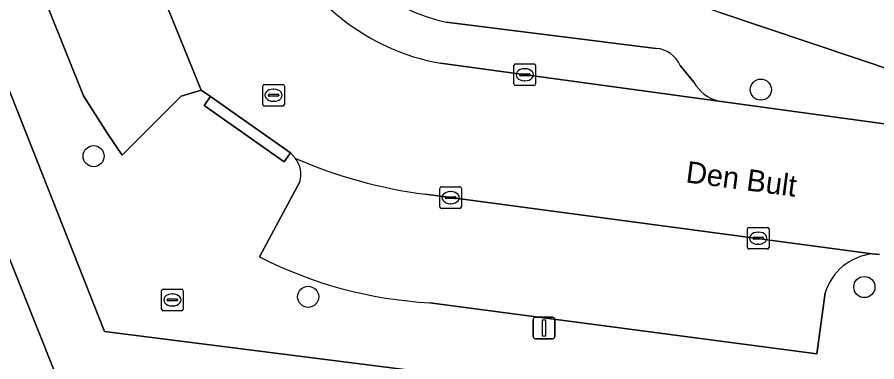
# Model space of a CAD drawing. Extents: x 159716 to 160783, y 383290 to 384031.
# Drawn here: x 160012.06 to 160051.81, y 383381.02 to 383396.98 of the extents above; entities that cross this region are included whole.
import ezdxf

# ---------------------------------------------------------------- set-up
doc = ezdxf.new("R2010")
doc.units = 0
for name, color, linetype in [('IMGEO_Boom', 7, 'Continuous'), ('IMGEO_Brandkraan', 7, 'Continuous'), ('IMGEO_Erf', 7, 'Continuous'), ('IMGEO_Kolk', 7, 'Continuous'), ('IMGEO_Lichtmast', 7, 'Continuous'), ('IMGEO_Openbare_ruimte_label', 7, 'Continuous'), ('IMGEO_Pand', 7, 'Continuous'), ('IMGEO_Parkeervlak_open', 7, 'Continuous'), ('IMGEO_Rijbaan_lokaal_open', 7, 'Continuous'), ('IMGEO_Rioolput', 7, 'Continuous'), ('IMGEO_Voetpad_open', 7, 'Continuous')]:
    doc.layers.add(name, color=color, linetype=linetype)

msp = doc.modelspace()

# ---------------------------------------------------------------- linework, layer by layer
at = {"layer": 'IMGEO_Boom'}
for centre in [(160046.451, 383393.623), (160015.592, 383390.544), (160051.24, 383384.484), (160025.516, 383384.034)]:
    msp.add_circle(centre, 0.489, dxfattribs=at)
at = {"layer": 'IMGEO_Brandkraan'}
for p, q in [((160018.738, 383383.463), (160018.738, 383384.315)), ((160018.813, 383384.389), (160019.665, 383384.389)), ((160019.739, 383384.315), (160019.739, 383383.463)), ((160018.997, 383383.883), (160018.997, 383383.895)), ((160019.435, 383383.846), (160019.037, 383383.846)), ((160019.04, 383383.932), (160019.438, 383383.932)), ((160019.226, 383384.169), (160019.251, 383384.169)), ((160019.481, 383383.895), (160019.481, 383383.883)), ((160019.249, 383383.609), (160019.224, 383383.609)), ((160019.665, 383383.389), (160018.813, 383383.389))]:
    msp.add_line(p, q, dxfattribs=at)
for points in [[(160018.738, 383383.463), (160018.738, 383384.315)], [(160018.813, 383384.389), (160019.665, 383384.389)], [(160019.739, 383384.315), (160019.739, 383383.463)], [(160019.665, 383383.389), (160018.813, 383383.389)]]:
    msp.add_lwpolyline(points, dxfattribs=at)
for centre, radius, start, end in [((160018.815, 383384.313), 0.0765, 91.552, 178.448), ((160018.815, 383384.313), 0.0765, 91.552, 178.448), ((160019.663, 383384.313), 0.0765, 1.552, 88.448), ((160019.663, 383384.313), 0.0765, 1.552, 88.448), ((160019.037, 383383.892), 0.0403, 85.8775, 175.7526), ((160019.034, 383383.882), 0.0366, 178.938, 274.7102), ((160019.438, 383383.889), 0.043, 264.8664, 352.4533), ((160019.442, 383383.894), 0.0386, 1.7309, 96.639), ((160018.815, 383383.465), 0.0765, 181.552, 268.448), ((160018.815, 383383.465), 0.0765, 181.552, 268.448), ((160019.663, 383383.465), 0.0765, 271.552, 358.448), ((160019.663, 383383.465), 0.0765, 271.552, 358.448)]:
    msp.add_arc(centre, radius, start, end, dxfattribs=at)
for centre, major_axis, ratio, start_param, end_param in [((160019.225, 383383.889), (-0.387, 0.002), 0.722429, 4.712389, 7.853982), ((160019.25, 383383.889), (-0.39, 0.002), 0.717154, 1.570796, 4.712389)]:
    msp.add_ellipse(centre, major_axis=major_axis, ratio=ratio, start_param=start_param, end_param=end_param, dxfattribs=at)
at = {"layer": 'IMGEO_Erf'}
for points in [[(160000.81, 383413.031), (160002.876, 383407.864), (160004.895, 383402.814), (160006.914, 383397.764), (160008.934, 383392.713), (160010.953, 383387.663), (160014.825, 383377.98), (160018.263, 383377.541), (160018.539, 383379.697), (160024.297, 383378.96), (160029.935, 383378.239), (160035.574, 383377.518), (160041.212, 383376.797), (160046.85, 383376.076), (160052.624, 383375.337), (160052.976, 383377.756), (160016.099, 383382.429), (160004.346, 383412.176)], [(160044.548, 383397.2), (160052.814, 383394.42)]]:
    msp.add_lwpolyline(points, dxfattribs=at)
at = {"layer": 'IMGEO_Kolk'}
for p, q in [((160035.033, 383393.885), (160035.033, 383394.737)), ((160035.108, 383394.811), (160035.96, 383394.811)), ((160035.521, 383394.591), (160035.546, 383394.591)), ((160036.034, 383394.737), (160036.034, 383393.885)), ((160035.292, 383394.305), (160035.292, 383394.317)), ((160035.73, 383394.268), (160035.332, 383394.268)), ((160035.335, 383394.354), (160035.733, 383394.354)), ((160035.776, 383394.317), (160035.776, 383394.305)), ((160035.96, 383393.811), (160035.108, 383393.811)), ((160035.544, 383394.031), (160035.519, 383394.031)), ((160031.604, 383388.197), (160031.604, 383389.049)), ((160031.679, 383389.123), (160032.531, 383389.123)), ((160032.605, 383389.049), (160032.605, 383388.197)), ((160031.863, 383388.617), (160031.863, 383388.629)), ((160031.906, 383388.666), (160032.304, 383388.666)), ((160032.092, 383388.903), (160032.117, 383388.903)), ((160032.347, 383388.629), (160032.347, 383388.617)), ((160032.301, 383388.58), (160031.903, 383388.58)), ((160032.115, 383388.343), (160032.09, 383388.343)), ((160032.531, 383388.123), (160031.679, 383388.123)), ((160045.829, 383386.32), (160045.829, 383387.172)), ((160045.904, 383387.246), (160046.756, 383387.246)), ((160046.317, 383387.026), (160046.342, 383387.026)), ((160046.83, 383387.172), (160046.83, 383386.32)), ((160046.088, 383386.74), (160046.088, 383386.752)), ((160046.526, 383386.703), (160046.128, 383386.703)), ((160046.131, 383386.789), (160046.529, 383386.789)), ((160046.572, 383386.752), (160046.572, 383386.74)), ((160046.756, 383386.246), (160045.904, 383386.246)), ((160046.34, 383386.466), (160046.315, 383386.466))]:
    msp.add_line(p, q, dxfattribs=at)
for points in [[(160035.033, 383393.885), (160035.033, 383394.737)], [(160035.108, 383394.811), (160035.96, 383394.811)], [(160036.034, 383394.737), (160036.034, 383393.885)], [(160035.96, 383393.811), (160035.108, 383393.811)], [(160031.604, 383388.197), (160031.604, 383389.049)], [(160031.679, 383389.123), (160032.531, 383389.123)], [(160032.605, 383389.049), (160032.605, 383388.197)], [(160032.531, 383388.123), (160031.679, 383388.123)], [(160045.829, 383386.32), (160045.829, 383387.172)], [(160045.904, 383387.246), (160046.756, 383387.246)], [(160046.83, 383387.172), (160046.83, 383386.32)], [(160046.756, 383386.246), (160045.904, 383386.246)]]:
    msp.add_lwpolyline(points, dxfattribs=at)
for centre, radius, start, end in [((160035.11, 383394.735), 0.0765, 91.552, 178.448), ((160035.11, 383394.735), 0.0765, 91.552, 178.448), ((160035.958, 383394.735), 0.0765, 1.552, 88.448), ((160035.958, 383394.735), 0.0765, 1.552, 88.448), ((160035.332, 383394.314), 0.0403, 85.8775, 175.7526), ((160035.329, 383394.304), 0.0366, 178.938, 274.7102), ((160035.733, 383394.311), 0.043, 264.8664, 352.4533), ((160035.737, 383394.316), 0.0386, 1.7309, 96.639), ((160035.11, 383393.887), 0.0765, 181.552, 268.448), ((160035.11, 383393.887), 0.0765, 181.552, 268.448), ((160035.958, 383393.887), 0.0765, 271.552, 358.448), ((160035.958, 383393.887), 0.0765, 271.552, 358.448), ((160031.681, 383389.047), 0.0765, 91.552, 178.448), ((160031.681, 383389.047), 0.0765, 91.552, 178.448), ((160032.529, 383389.047), 0.0765, 1.552, 88.448), ((160032.529, 383389.047), 0.0765, 1.552, 88.448), ((160031.903, 383388.626), 0.0403, 85.8775, 175.7526), ((160031.9, 383388.616), 0.0366, 178.938, 274.7102), ((160032.304, 383388.623), 0.043, 264.8664, 352.4533), ((160032.308, 383388.628), 0.0386, 1.7309, 96.639), ((160031.681, 383388.199), 0.0765, 181.552, 268.448), ((160031.681, 383388.199), 0.0765, 181.552, 268.448), ((160032.529, 383388.199), 0.0765, 271.552, 358.448), ((160032.529, 383388.199), 0.0765, 271.552, 358.448), ((160045.906, 383387.17), 0.0765, 91.552, 178.448), ((160045.906, 383387.17), 0.0765, 91.552, 178.448), ((160046.754, 383387.17), 0.0765, 1.552, 88.448), ((160046.754, 383387.17), 0.0765, 1.552, 88.448), ((160046.128, 383386.749), 0.0403, 85.8775, 175.7526), ((160046.125, 383386.739), 0.0366, 178.938, 274.7102), ((160046.529, 383386.746), 0.043, 264.8664, 352.4533), ((160046.533, 383386.751), 0.0386, 1.7309, 96.639), ((160045.906, 383386.322), 0.0765, 181.552, 268.448), ((160045.906, 383386.322), 0.0765, 181.552, 268.448), ((160046.754, 383386.322), 0.0765, 271.552, 358.448), ((160046.754, 383386.322), 0.0765, 271.552, 358.448)]:
    msp.add_arc(centre, radius, start, end, dxfattribs=at)
for centre, major_axis, ratio, start_param, end_param in [((160035.52, 383394.311), (-0.387, 0.002), 0.722429, 4.712389, 7.853982), ((160035.545, 383394.311), (-0.39, 0.002), 0.717154, 1.570796, 4.712389), ((160032.091, 383388.623), (-0.387, 0.002), 0.722429, 4.712389, 7.853982), ((160032.116, 383388.623), (-0.39, 0.002), 0.717154, 1.570796, 4.712389), ((160046.316, 383386.746), (-0.387, 0.002), 0.722429, 4.712389, 7.853982), ((160046.341, 383386.746), (-0.39, 0.002), 0.717154, 1.570796, 4.712389)]:
    msp.add_ellipse(centre, major_axis=major_axis, ratio=ratio, start_param=start_param, end_param=end_param, dxfattribs=at)
at = {"layer": 'IMGEO_Lichtmast'}
for p, q in [((160036.029, 383383.09), (160036.819, 383383.09)), ((160036.819, 383383.09), (160036.029, 383383.09)), ((160035.929, 383382.19), (160035.929, 383382.99)), ((160035.929, 383382.99), (160035.929, 383382.19)), ((160036.919, 383382.99), (160036.919, 383382.19)), ((160036.919, 383382.19), (160036.919, 383382.99)), ((160036.819, 383382.09), (160036.029, 383382.09)), ((160036.029, 383382.09), (160036.819, 383382.09))]:
    msp.add_line(p, q, dxfattribs=at)
msp.add_lwpolyline([(160036.349, 383382.965), (160036.499, 383382.965), (160036.499, 383382.215), (160036.349, 383382.215), (160036.349, 383382.965)], dxfattribs=at)
for centre, start, end in [((160036.029, 383382.99), 90, 180), ((160036.029, 383382.99), 90, 180), ((160036.819, 383382.99), 0, 90), ((160036.819, 383382.99), 360, 90), ((160036.029, 383382.19), 180, 270), ((160036.029, 383382.19), 180, 270), ((160036.819, 383382.19), 270, 0), ((160036.819, 383382.19), 270, 0)]:
    msp.add_arc(centre, 0.1, start, end, dxfattribs=at)
at = {"layer": 'IMGEO_Pand'}
msp.add_lwpolyline([(160003.449, 383384.662), (160006.055, 383378.145), (160008.19, 383378.998), (160010.623, 383373.014), (160014.825, 383377.98), (160010.953, 383387.663)], close=True, dxfattribs=at)
at = {"layer": 'IMGEO_Parkeervlak_open'}
for points in [[(160010.124, 383414.551), (160007.087, 383413.335), (160015.132, 383393.329), (160016.239, 383391.585), (160016.912, 383390.595), (160019.641, 383393.313), (160020.572, 383393.598), (160016.582, 383403.447), (160011.17, 383416.862)], [(160041.606, 383395.532), (160031.897, 383396.753)], [(160031.637, 383394.841), (160044.505, 383393.088)], [(160043.345, 383393.971), (160042.723, 383394.733)], [(160025.127, 383389.354), (160023.261, 383385.888)], [(160051.595, 383386.022), (160030.94, 383388.777)], [(160031.145, 383383.758), (160049.047, 383381.392), (160049.428, 383384.224)]]:
    msp.add_lwpolyline(points, dxfattribs=at)
for centre, radius, start, end in [((160033.754, 383405.228), 8.676, 205.1112, 257.6415), ((160033.452, 383404.956), 10.276, 203.0028, 259.8259), ((160041.507, 383394.213), 1.323, 23.1563, 85.6907), ((160044.989, 383394.928), 1.902, 210.1891, 255.2536), ((160033.905, 383411.181), 22.6, 246.5895, 262.4606), ((160023.975, 383389.704), 1.204, 343.1064, 37.8275), ((160032.179, 383403.243), 19.512, 242.802, 266.961), ((160051.89, 383383.462), 2.577, 96.565, 162.8012)]:
    msp.add_arc(centre, radius, start, end, dxfattribs=at)
at = {"layer": 'IMGEO_Rijbaan_lokaal_open'}
for points in [[(160011.17, 383416.862), (160016.582, 383403.447), (160020.572, 383393.598), (160020.994, 383393.3), (160024.693, 383390.692), (160024.926, 383390.442)], [(160053.062, 383391.922), (160044.505, 383393.088), (160031.637, 383394.841)], [(160030.94, 383388.777), (160051.595, 383386.022), (160051.765, 383386.007), (160051.935, 383385.999)]]:
    msp.add_lwpolyline(points, dxfattribs=at)
for centre, radius, start, end in [((160033.452, 383404.956), 10.276, 203.0028, 259.8259), ((160033.905, 383411.181), 22.6, 246.5895, 262.4606)]:
    msp.add_arc(centre, radius, start, end, dxfattribs=at)
at = {"layer": 'IMGEO_Rioolput'}
for p, q in [((160023.416, 383392.938), (160023.416, 383393.79)), ((160023.491, 383393.864), (160024.343, 383393.864)), ((160024.417, 383393.79), (160024.417, 383392.938)), ((160023.718, 383393.407), (160024.116, 383393.407)), ((160023.904, 383393.644), (160023.929, 383393.644)), ((160023.675, 383393.358), (160023.675, 383393.37)), ((160024.113, 383393.321), (160023.715, 383393.321)), ((160023.927, 383393.084), (160023.902, 383393.084)), ((160024.159, 383393.37), (160024.159, 383393.358)), ((160024.343, 383392.864), (160023.491, 383392.864))]:
    msp.add_line(p, q, dxfattribs=at)
for points in [[(160023.416, 383392.938), (160023.416, 383393.79)], [(160023.491, 383393.864), (160024.343, 383393.864)], [(160024.417, 383393.79), (160024.417, 383392.938)], [(160024.343, 383392.864), (160023.491, 383392.864)]]:
    msp.add_lwpolyline(points, dxfattribs=at)
for centre, radius, start, end in [((160023.493, 383393.788), 0.0765, 91.552, 178.448), ((160023.493, 383393.788), 0.0765, 91.552, 178.448), ((160024.341, 383393.788), 0.0765, 1.552, 88.448), ((160024.341, 383393.788), 0.0765, 1.552, 88.448), ((160023.715, 383393.367), 0.0403, 85.8775, 175.7526), ((160024.12, 383393.369), 0.0386, 1.7309, 96.639), ((160023.712, 383393.357), 0.0366, 178.938, 274.7102), ((160024.116, 383393.364), 0.043, 264.8664, 352.4533), ((160023.493, 383392.94), 0.0765, 181.552, 268.448), ((160023.493, 383392.94), 0.0765, 181.552, 268.448), ((160024.341, 383392.94), 0.0765, 271.552, 358.448), ((160024.341, 383392.94), 0.0765, 271.552, 358.448)]:
    msp.add_arc(centre, radius, start, end, dxfattribs=at)
for centre, major_axis, ratio, start_param, end_param in [((160023.903, 383393.364), (-0.387, 0.002), 0.722429, 4.712389, 7.853982), ((160023.928, 383393.364), (-0.39, 0.002), 0.717154, 1.570796, 4.712389)]:
    msp.add_ellipse(centre, major_axis=major_axis, ratio=ratio, start_param=start_param, end_param=end_param, dxfattribs=at)
at = {"layer": 'IMGEO_Voetpad_open'}
for points in [[(160024.926, 383390.442), (160024.693, 383390.692), (160024.405, 383390.284), (160020.706, 383392.892), (160020.994, 383393.3), (160020.572, 383393.598), (160019.641, 383393.313), (160016.912, 383390.595), (160016.239, 383391.585), (160015.132, 383393.329), (160007.087, 383413.335), (160010.124, 383414.551)], [(160004.346, 383412.176), (160016.099, 383382.429), (160052.976, 383377.756), (160052.624, 383375.337), (160052.439, 383373.892), (160053.714, 383373.727), (160055.073, 383373.551), (160085.3, 383369.646), (160086.667, 383374.185)], [(160059.374, 383392.494), (160052.814, 383394.42), (160044.548, 383397.2), (160043.108, 383397.684), (160041.813, 383398.119), (160033.088, 383399.276), (160032.2, 383399.447)], [(160031.897, 383396.753), (160041.606, 383395.532)], [(160042.723, 383394.733), (160043.345, 383393.971)], [(160044.505, 383393.088), (160053.062, 383391.922)], [(160023.261, 383385.888), (160025.127, 383389.354)], [(160051.935, 383385.999), (160051.765, 383386.007), (160051.595, 383386.022)], [(160049.428, 383384.224), (160049.047, 383381.392), (160031.145, 383383.758)]]:
    msp.add_lwpolyline(points, dxfattribs=at)
msp.add_lwpolyline([(160024.693, 383390.692), (160020.994, 383393.3), (160020.706, 383392.892), (160024.405, 383390.284)], close=True, dxfattribs=at)
for centre, radius, start, end in [((160033.754, 383405.228), 8.676, 205.1112, 257.6415), ((160041.507, 383394.213), 1.323, 23.1563, 85.6907), ((160044.989, 383394.928), 1.902, 210.1891, 255.2536), ((160023.975, 383389.704), 1.204, 343.1064, 37.8275), ((160032.179, 383403.243), 19.512, 242.802, 266.961), ((160051.89, 383383.462), 2.577, 96.565, 162.8012)]:
    msp.add_arc(centre, radius, start, end, dxfattribs=at)

# ---------------------------------------------------------------- texts
at = {"layer": 'IMGEO_Openbare_ruimte_label'}
msp.add_text('Den Bult', height=1, rotation=352.4697, dxfattribs=at).set_placement((160042.946, 383389.333))

doc.saveas('drawing.dxf')
